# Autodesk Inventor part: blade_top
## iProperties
Shininess: 100.0
Length Units: 11269
Angle Units: 11279
Time Units: 11290
Mass Units: 11283
Length Display Precision: 3
Angle Display Precision: 2
Compacted: True
Manager: Lebovitz
Company: Autodesk
Created: 2000-05
Part Number: blade_top
Document SubType Name: Modeling
Designer: The PD Team
Project: Inventor Samples
Density: 1 g/cm^3
Density: 0.0
Volumn: 0.0
Area: 0.0
PropertySet Name: Model Information
Control State: 0
Master: False
Checked Out: False
Author: The PD Team
Revision Number: A
